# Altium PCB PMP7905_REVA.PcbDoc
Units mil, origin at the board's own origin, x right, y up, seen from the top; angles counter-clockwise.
Board outline 3200 x 2800 mil, 4 copper layers (Top Layer, MidLayer1, MidLayer2, Bottom Layer), stack 62 mil thick; 91 components, 31 nets, 190 pads, 69 vias.
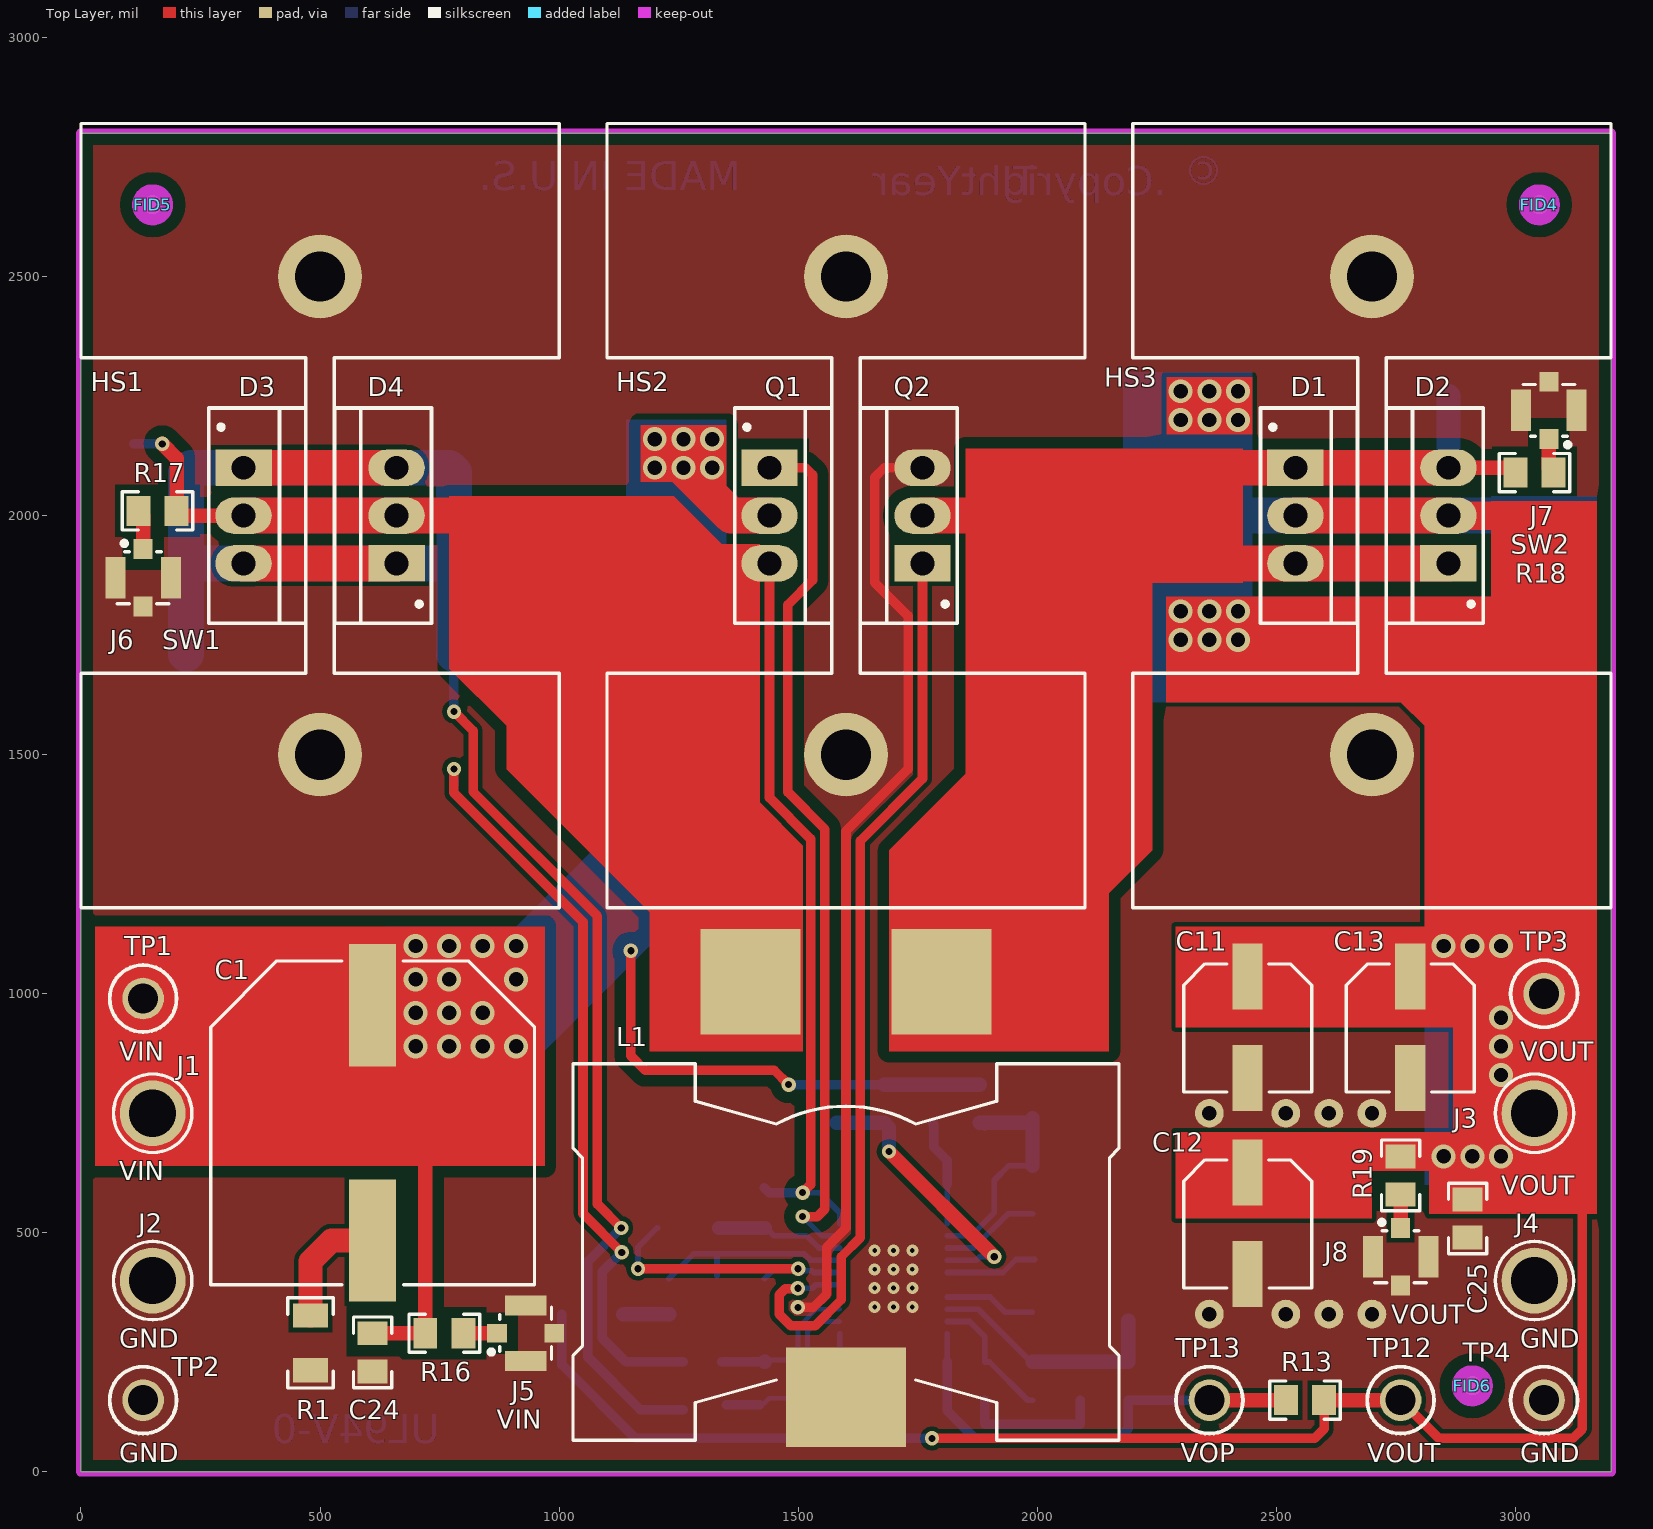
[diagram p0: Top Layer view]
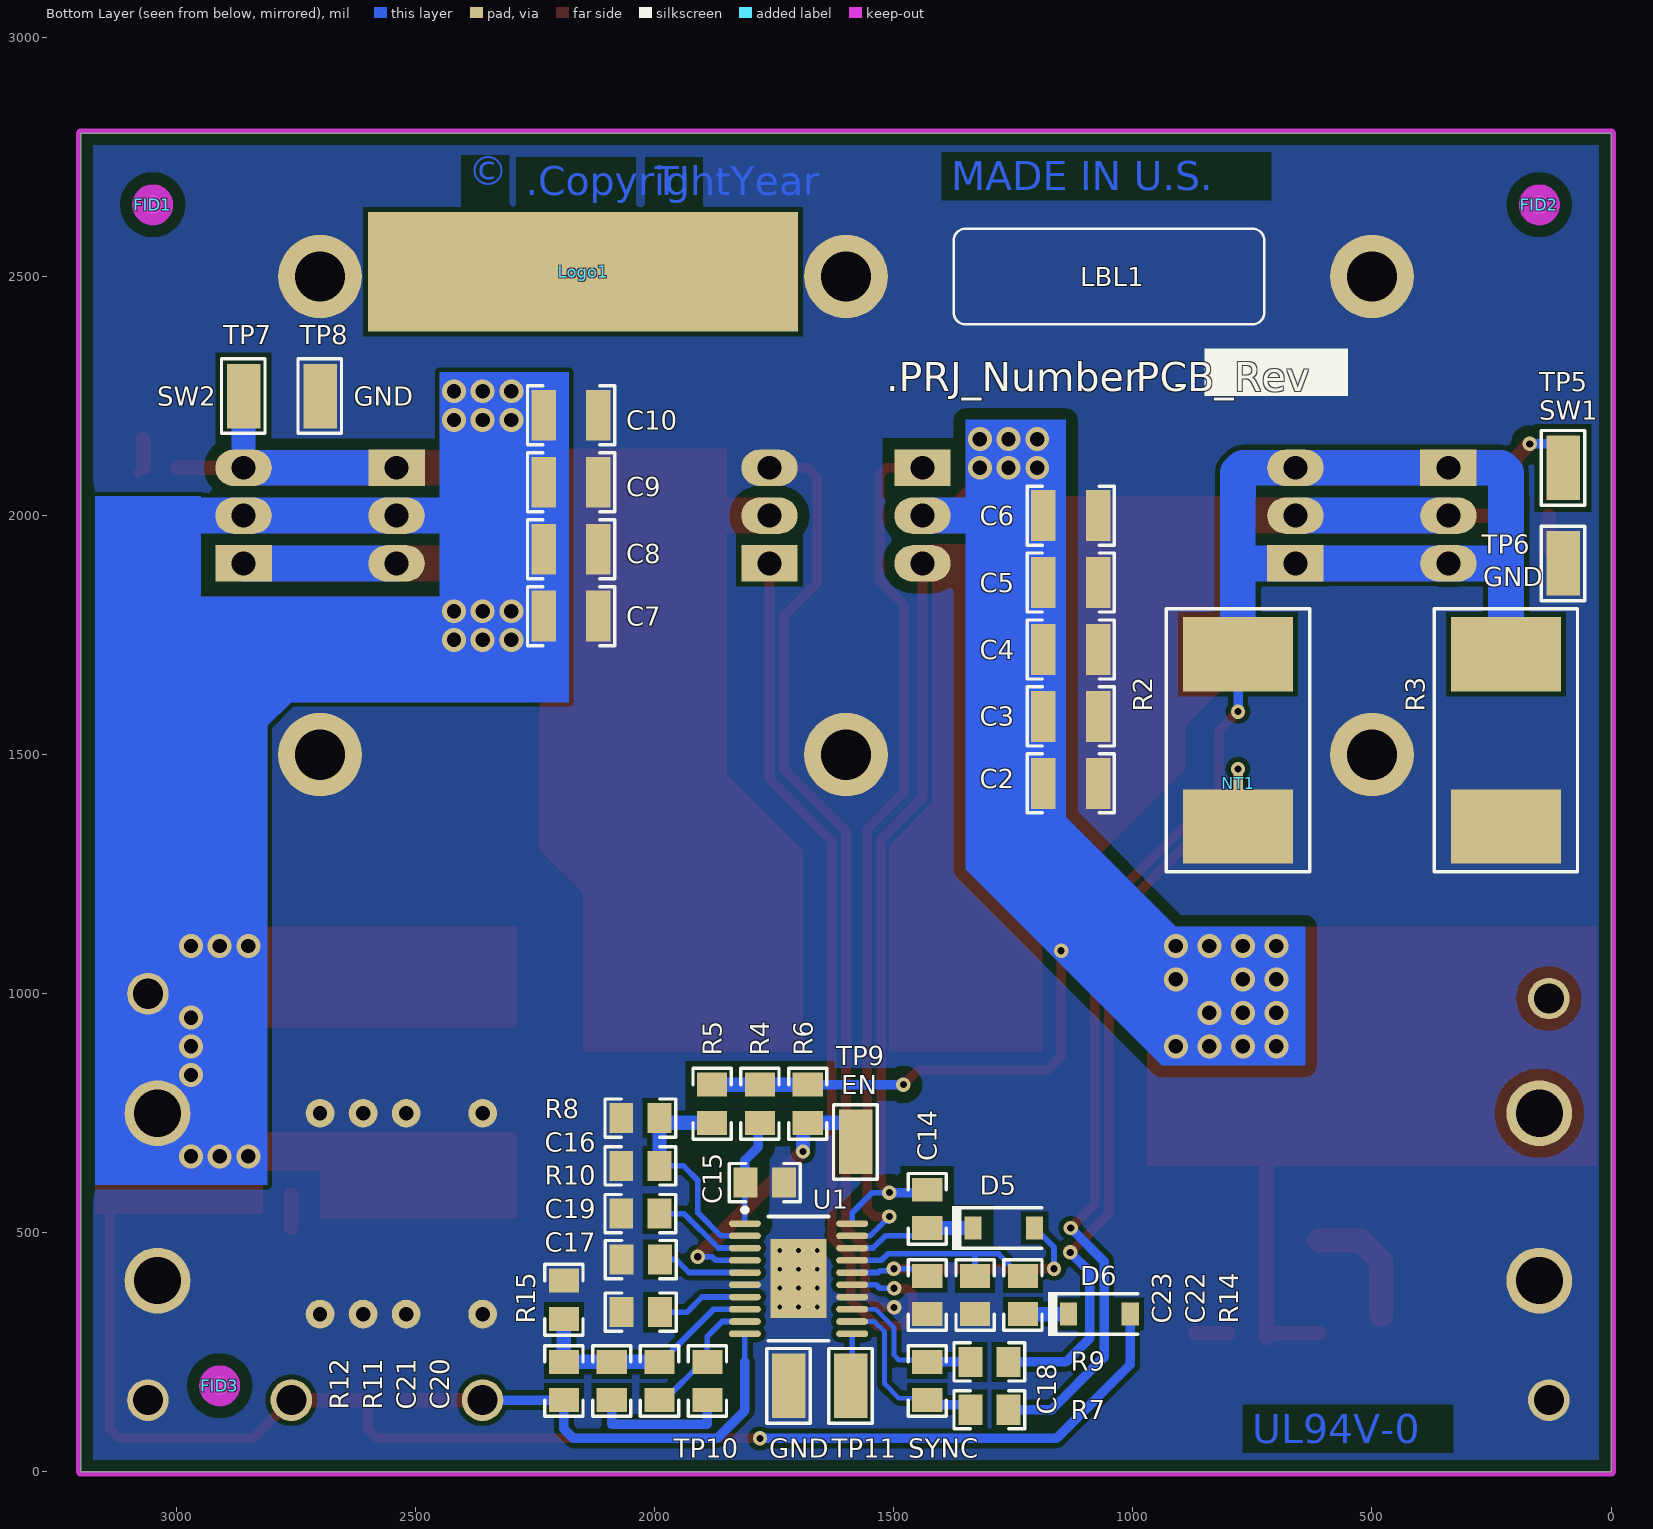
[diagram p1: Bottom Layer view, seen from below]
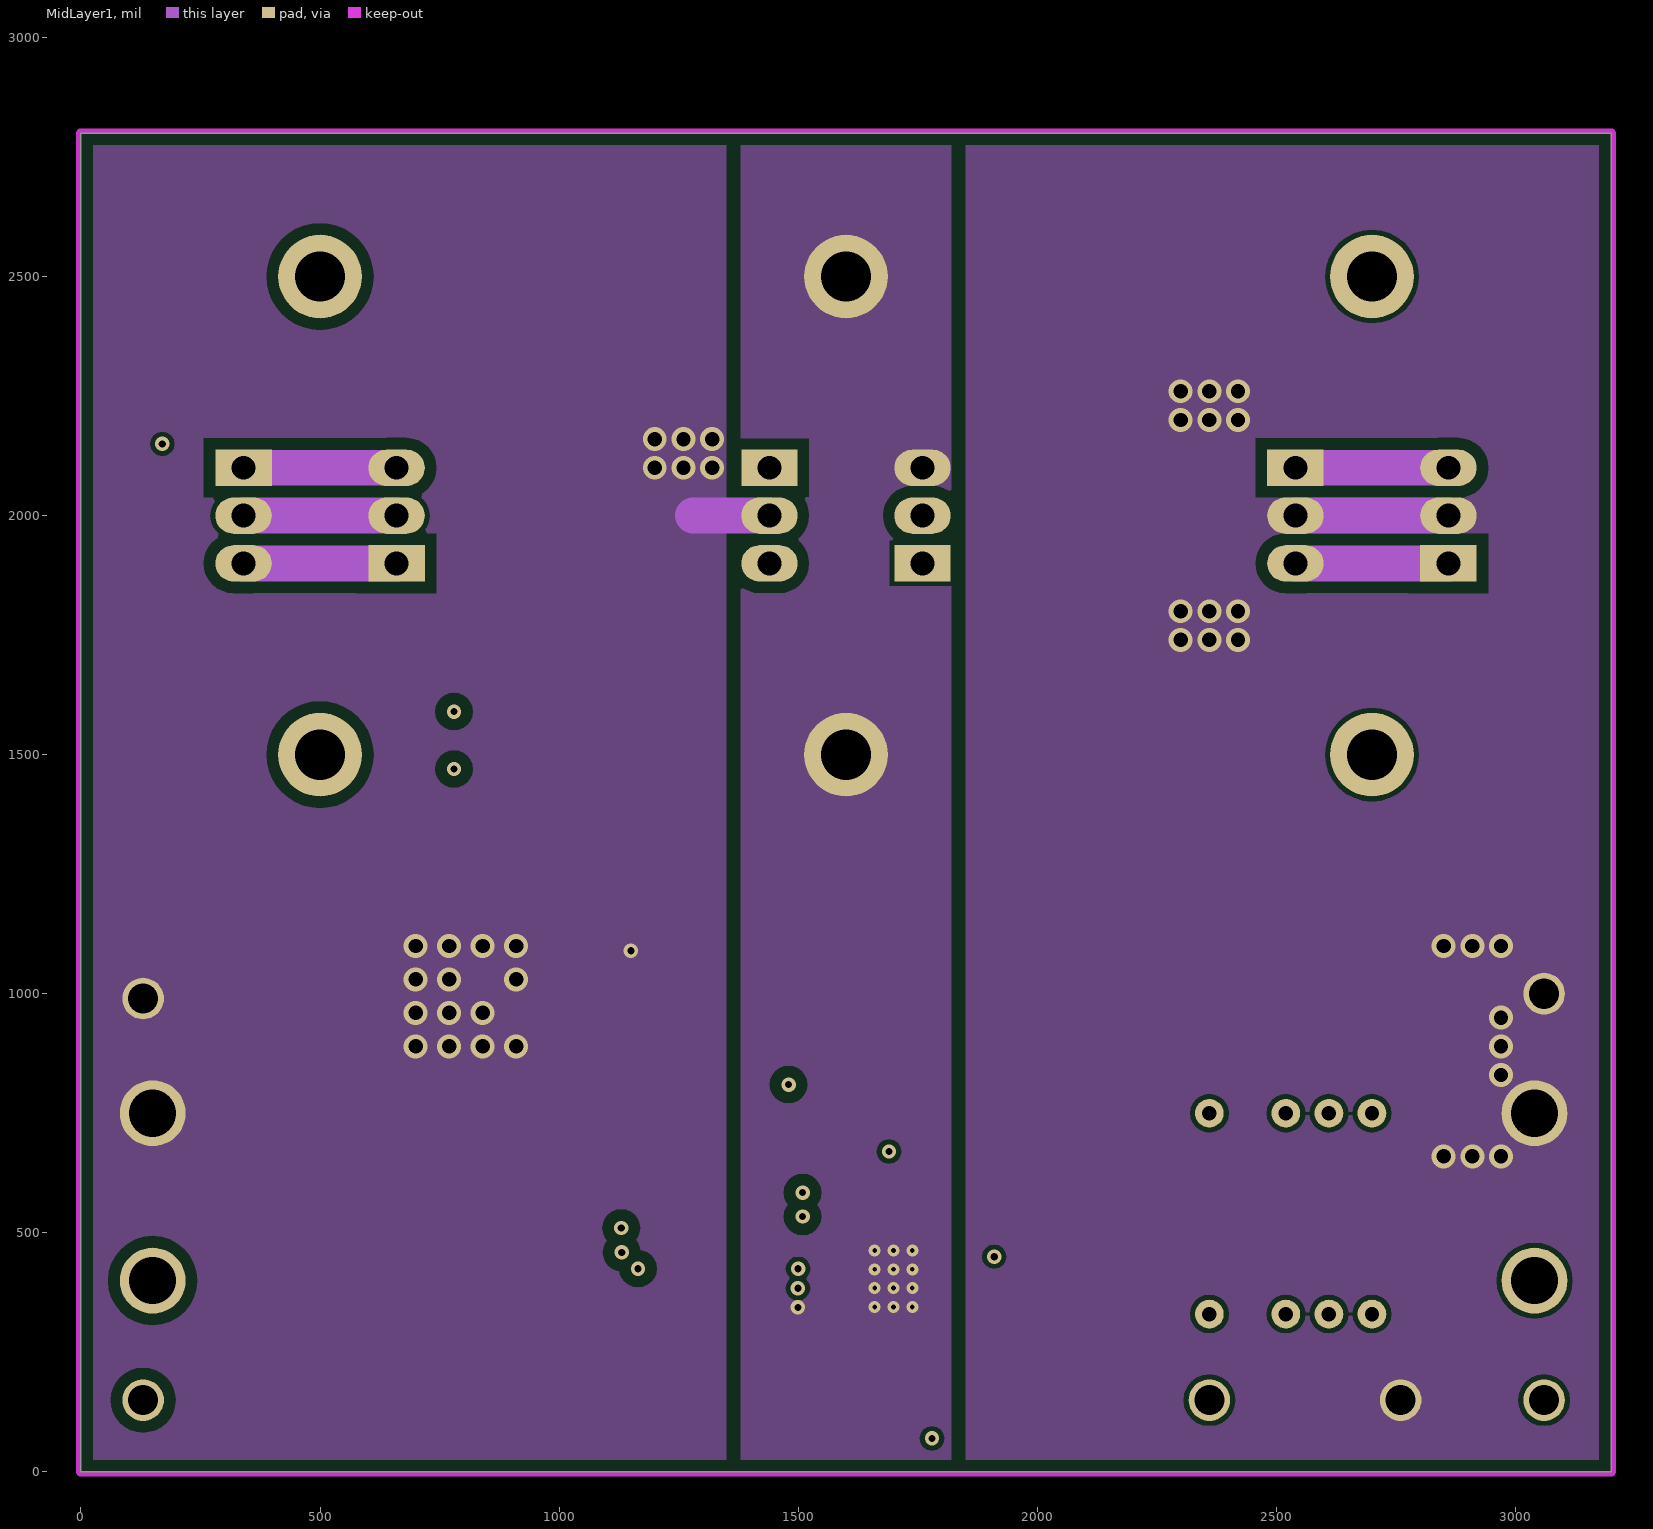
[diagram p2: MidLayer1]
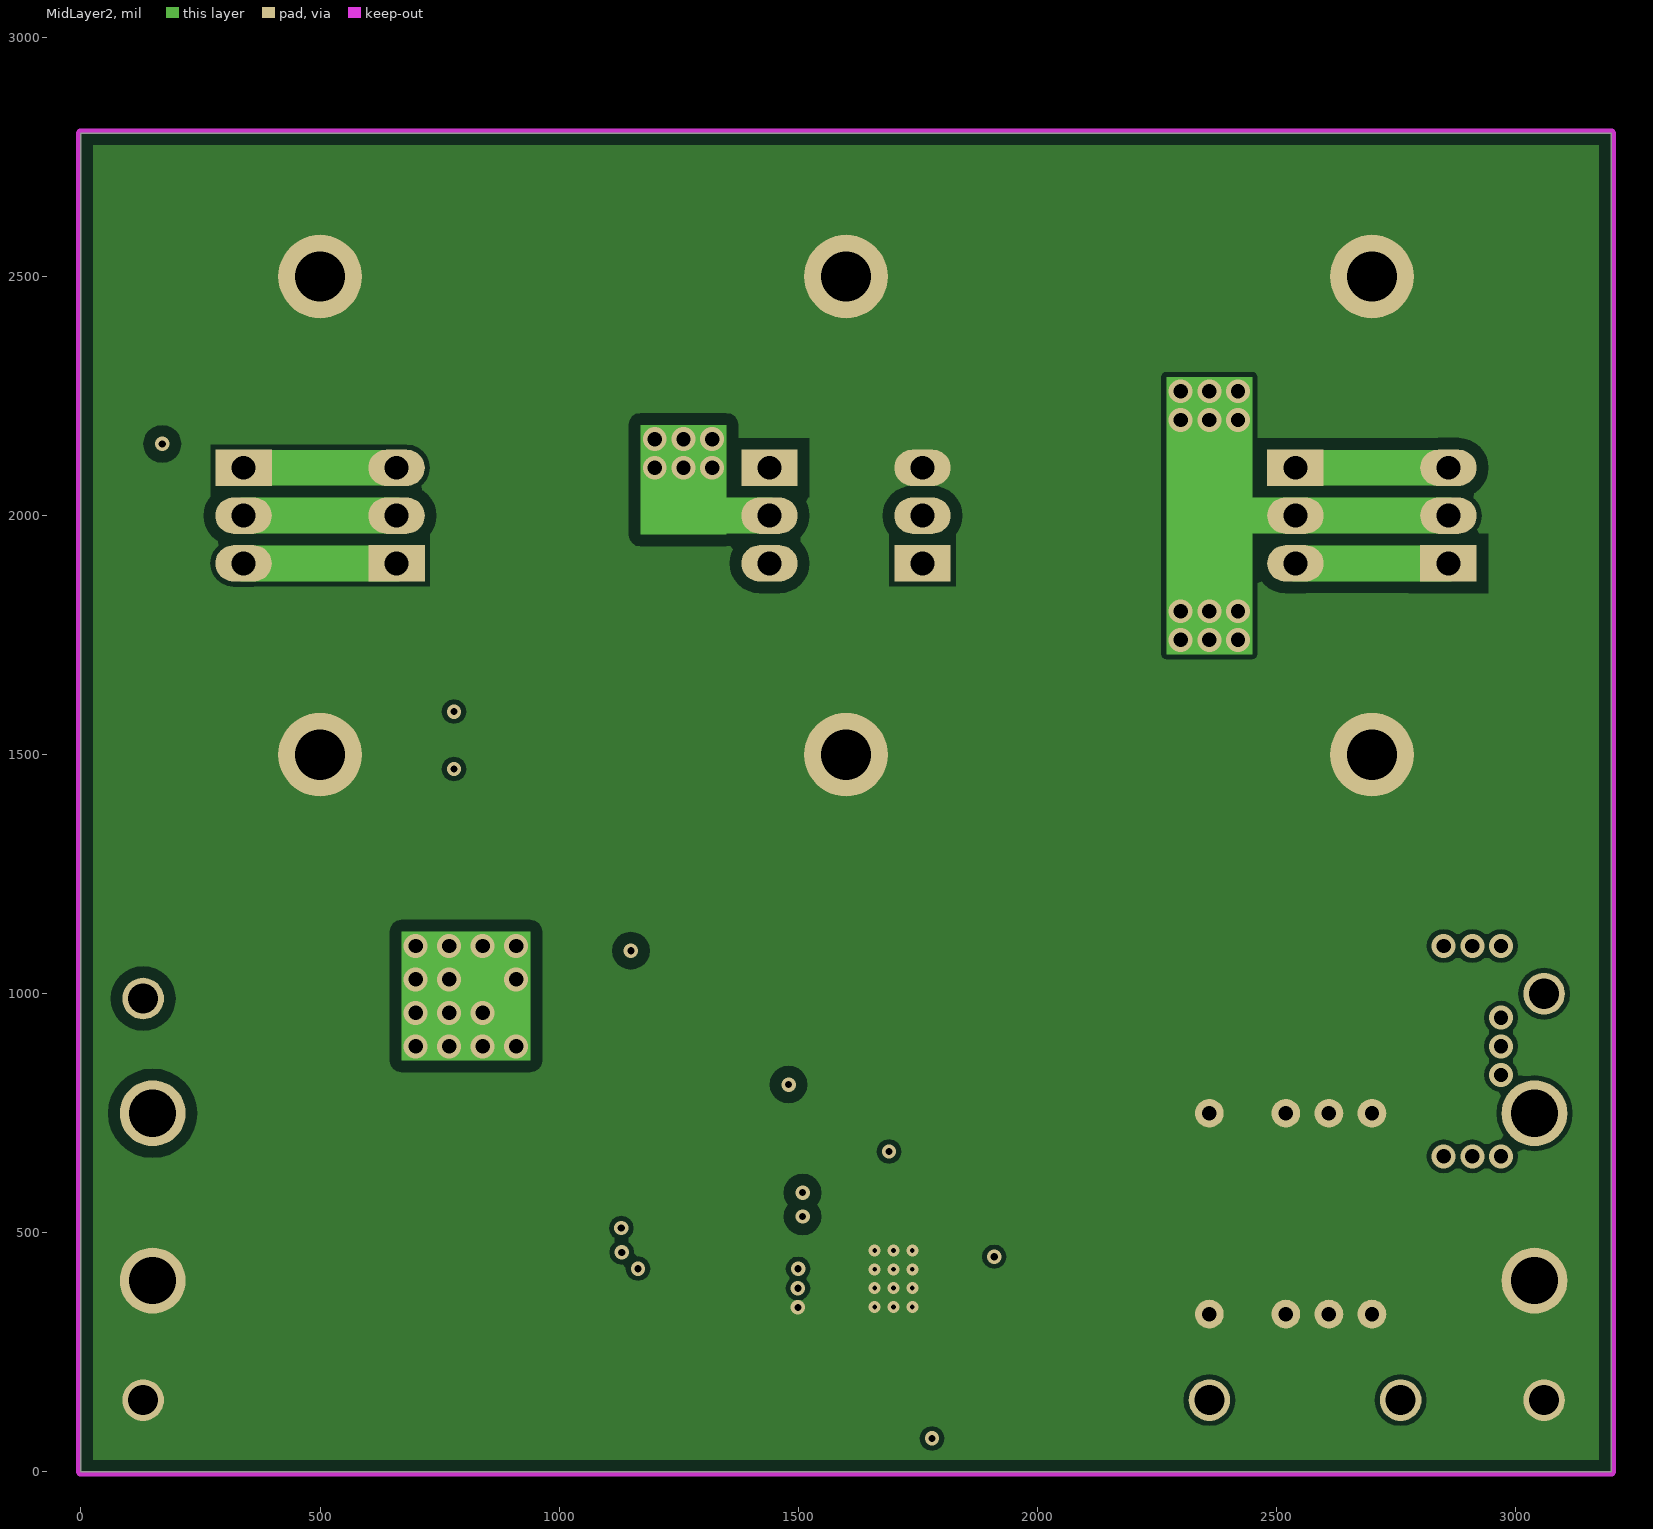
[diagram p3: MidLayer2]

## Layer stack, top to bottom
Top Layer: signal copper 2.8
Dielectric: core 12.6, FR-4, Dk 4.8
MidLayer1: signal copper 1.4
Dielectric: prepreg 28.4, FR-4, Dk 4.8
MidLayer2: signal copper 1.4
Dielectric: core 12.6, FR-4, Dk 4.8
Bottom Layer: signal copper 2.8

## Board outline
0,0 3200,0 3200,2800 0,2800

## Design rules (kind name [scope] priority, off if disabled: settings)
AcuteAngle [All] p1: minimum=4.50000000000000E+0001 checktracksonly=FALSE
AssemblyTestPointUsage [All] p1: valid=2
Clearance Clearance_A-1JB [HasFootprint('A-1JB') vs InNetClass('24mil')] p1: gap=17.5
Clearance Clearance_MXA20A_N [HasFootprint('MXA20A_N') vs InNetClass('24mil')] p2: gap=11
Clearance Clearance_HB_VCCX [InNet('HB') vs InNet('VCCX')] p3: gap=12.5
Clearance Clearance_UVLO_VINF [InNet('UVLO') vs InNet('VINF')] p4: gap=12
Clearance Clearance_10mil_24mil [InNetClass('10mil') vs InNetClass('24mil')] p5: gap=24
Clearance Clearance_BoardEdge_MountingHoles [OnCopper and InComponentClass('Mounting Holes') vs IsKeepOut] p6: gap=40
Clearance Clearance_BoardEdge_Poly [OnCopper and (InPoly or IsRegion) vs IsKeepOut] p7: gap=25
Clearance Clearance_BoardEdge [OnCopper and Not InComponentClass('Logo') and not InComponentClass('FiducialMark') and not InRegion(1000,500,4000,800) vs IsKeepOut] p8: gap=50
Clearance [All] p9: gap=10
ComponentClearance ComponentClearance_NetTie [HasFootprint('Net-Tie_20mil') vs HasFootprint('4527')] p1: gap=0 collisioncheckmode=3 verticalgap=0 showdistances=FALSE
ComponentClearance ComponentClearance_Fiducial_HS [HasFootprint('Fiducial10-20_TopLayerKeepOutOnly') vs HasFootprint('HS-TO-220-VERT-1')] p2: gap=0 collisioncheckmode=3 verticalgap=0 showdistances=FALSE
ComponentClearance ComponentClearance_Fiducial [HasFootprint('Fiducial10-20_TopLayerKeepOutOnly')] p3: gap=40 collisioncheckmode=3 verticalgap=0 showdistances=FALSE
ComponentClearance ComponentClearance_TO-220 [HasFootprint('TO-220AB') vs HasFootprint('TO-220AB')] p4: gap=60 collisioncheckmode=3 verticalgap=10 showdistances=FALSE
ComponentClearance ComponentClearance_HeatSink [HasFootprint('HS-TO-220-VERT-1') vs HasFootprint('TO-220AB')] p5: gap=0 collisioncheckmode=3 verticalgap=10 showdistances=FALSE
ComponentClearance ComponentClearance_Logo [InComponentClass(Logo)] p6: gap=50 collisioncheckmode=3 verticalgap=10 showdistances=FALSE
ComponentClearance ComponentClearance_ScrewToNut [(HasFootprint('NY PMS 440 0025 PH')) vs (HasFootprint('Keystone_1902C'))] p7: gap=5 collisioncheckmode=3 verticalgap=10 showdistances=FALSE
ComponentClearance ComponentClearance_MountingHoles [InComponentClass('Mounting Holes')] p8: gap=150 collisioncheckmode=3 verticalgap=100000 showdistances=FALSE
ComponentClearance ComponentClearance_SmallPassives [HasFootprint('0201*') or HasFootprint('0402*') or HasFootprint('0508') or HasFootprint('0603*') or HasFootprint('0612') or HasFootprint('0805*') or HasFootprint('0815*') or HasFootprint('0830*') or HasFootprint('1206*') or HasFootprint('1210*') or HasFootprint('1808*') or HasFootprint('1812*') or HasFootprint('1825*') or HasFootprint('2010*') or HasFootprint('2220*') or HasFootprint('2225*') or HasFootprint('2512*') or HasFootprint('2728*') or HasFootprint('3518*') vs HasFootprint('0201*') or HasFootprint('0402*') or HasFootprint('0508') or HasFootprint('0603*') or HasFootprint('0612') or HasFootprint('0805*') or HasFootprint('0815*') or HasFootprint('0830*') or HasFootprint('1206*') or HasFootprint('1210*') or HasFootprint('1808*') or HasFootprint('1812*') or HasFootprint('1825*') or HasFootprint('2010*') or HasFootprint('2220*') or HasFootprint('2225*') or HasFootprint('2512*') or HasFootprint('2728*') or HasFootprint('3518*')] p9: gap=20 collisioncheckmode=3 verticalgap=10 showdistances=FALSE
ComponentClearance ComponentClearance_THtoSMT [IsThruComponent vs IsSMTComponent] p10: gap=50 collisioncheckmode=3 verticalgap=50 showdistances=FALSE
ComponentClearance ComponentClearance_THtoTH [IsThruComponent vs IsThruComponent] p11: gap=100 collisioncheckmode=3 verticalgap=50 showdistances=FALSE
ComponentClearance [All] p12: gap=40 collisioncheckmode=3 verticalgap=10 showdistances=FALSE
DiffPairsRouting [All] p1: maxlimit=100 minlimit=10 mostfreqgap=10 maxuncoupledlength=1000
FabricationTestPointUsage TestPointUsage [All] p1: valid=2 allowmultiple=FALSE
FabricationTestpoint Testpoint [All] p1: side=3 testpointundercomponent=TRUE minsize=40 maxsize=100 preferedsize=60 minholesize=0 maxholesize=40 preferedholesize=32 testpointgrid=1 allowsidetop=TRUE allowsidebottom=TRUE usegrid=TRUE gridtolerance=0.01
FanoutControl Fanout_LCC [IsLCC] p1: bgadir=Out bgaviamode=Centered fanoutstyle=Auto fanoutdirection=Alternating viagrid=1 // Fanout_LCC (Default Rule)
FanoutControl Fanout_BGA [IsBGA] p2: bgadir=Out bgaviamode=Centered fanoutstyle=Auto fanoutdirection=Alternating viagrid=1 // Fanout_BGA (Default Rule)
FanoutControl Fanout_Default [All] p4: bgadir=Out bgaviamode=Centered fanoutstyle=Auto fanoutdirection=Alternating viagrid=1 // Fanout_Default (Default Rule)
FanoutControl Fanout_Small [(CompPinCount < 5)] p5: bgadir=Out bgaviamode=Centered fanoutstyle=Auto fanoutdirection=OutThenIn viagrid=1 // Fanout_Small (Default Rule)
HoleSize [All] p1: absolutevalues=TRUE maxlimit=251 minlimit=8 maxpercent=80.000 minpercent=20.000
MinimumAnnularRing [All] p1: minimumring=7.5
MinimumSolderMaskSliver MinimumSolderMaskSliver_Logo [InComponentClass('Logo') vs InComponentClass('Logo')] p1: minsoldermaskwidth=0.7
MinimumSolderMaskSliver [All] p2: minsoldermaskwidth=4
PlaneConnect [All] p1: planeconnectstyle=Direct reliefexpansion=10 reliefentries=4 reliefconductorwidth=10 reliefairgap=10
PolygonConnect [All] p1: connectstyle=Direct reliefconductorwidth=10 reliefentries=4 polygonreliefangle="90 Angle" airgapwidth=10
RoutingVias [All] p1: holewidth=16 width=34 viastyle="Through Hole" minholewidth=8 minwidth=25 maxholewidth=40 maxwidth=65
SMDToCorner [All] p1: distance=30000
SilkToSilkClearance [All] p1: silktosilkclearance=5
SilkscreenOverComponentPads [All] p1: minsilkscreentomaskgap=5
SolderMaskExpansion [All] p1: expansion=3
Width [All] p1: maxlimit=100 minlimit=6 preferedwidth=10 checkconnectedcopper=TRUE
14 further rules are at their usual default settings.

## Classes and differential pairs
net class 24mil: HB HO SR1 SR2 SW1 SW2 VIN VINF VIR
net class 10mil: CMP COMP CS CSG CSN CSR EN FB GND LO RAMP RCIN RT SS SYNC UVLO VCC VCCD VCCX VOP VOR VOUT
component class Logo: Logo1
component class PMP7905_REVA_Hardware: FID1 FID2 FID3 FID4 FID5 FID6 HS1 HS2 HS3 LBL1 Logo1 ZZ1 ZZ2 ZZ3 ZZ4
component class FiducialMark: FID1 FID2 FID3 FID4 FID5 FID6
component class AssemblyNote: ZZ1 ZZ2 ZZ3 ZZ4
component class Label: LBL1

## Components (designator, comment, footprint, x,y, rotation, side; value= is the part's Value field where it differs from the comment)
C1 "EEV-FK2A101M" SM_RADIAL_J16 610,730 r270 top
C2 "C3225X7S2A475M" 1210 1130,1440 r180 bottom
C3 "C3225X7S2A475M" 1210 1130,1580 r180 bottom
C4 "C3225X7S2A475M" 1210 1130,1720 r180 bottom
C5 "C3225X7S2A475M" 1210 1130,1860 r180 bottom
C6 "C3225X7S2A475M" 1210 1130,2000 r180 bottom
C7 "GRM32ER61C476ME15L" 1210 2174.86,1789.77 r180 bottom
C8 "GRM32ER61C476ME15L" 1210 2174.85,1929.78 r180 bottom
C9 "GRM32ER61C476ME15L" 1210 2174.86,2069.77 r180 bottom
C10 "GRM32ER61C476ME15L" 1210 2174.86,2209.77 r180 bottom
C11 "APXE160ARA101MF80G" CAPSMT_62_F80 2440,930 r270 top
C12 "APXE160ARA101MF80G" CAPSMT_62_F80 2440,520 r270 top
C13 "APXE160ARA101MF80G" CAPSMT_62_F80 2780,930 r270 top
C14 "C2012X7R1E104K" 0805_HV 1430,550 r90 bottom
C15 "C2012X7R2A104K" 0805_HV 1770,605 r180 bottom
C16 "C2012X7R1E104K" 0805_HV 2030,640 r0 bottom
C17 "C2012X7R1E104K" 0805_HV 2029.32,334.01 r180 bottom
C18 "GRM216R71E102KA01D" 0805_HV 1430,190 r90 bottom
C19 "GRM2165C1H751JA01D" 0805_HV 2029.32,444.01 r180 bottom
C20 "GRM219R71E473KA01D" 0805_HV 1890,190 r90 bottom
C21 "C2012C0G1H101J" 0805_HV 1990,190 r270 bottom
C22 "C2012X7R1E105K" 0805_HV 1330,370 r270 bottom
C23 "C2012X7R1E105K" 0805_HV 1430,370 r270 bottom
C24 "C2012X7R2A104K" 0805_HV 610,250 r270 top
C25 "C2012X7R2A104K" 0805_HV 2900,530 r270 top
D1 "MBR2030CTL" TO-220AB 2540,2000 r270 top locked
D2 "MBR2030CTL" TO-220AB 2860,2000 r90 top locked
D3 "MBR30H100CT" TO-220AB 340,2000 r270 top locked
D4 "MBR30H100CT" TO-220AB 660,2000 r90 top locked
D5 "1N4148W-7-F" SOD-123 1270,510 r180 bottom
D6 "1N4148W-7-F" SOD-123 1070,330 r180 bottom
FID1 "Fiducial" Fiducial10-20_TopLayerKeepOutOnly 3050,2650 r180 bottom
FID2 "Fiducial" Fiducial10-20_TopLayerKeepOutOnly 150,2650 r180 bottom
FID3 "Fiducial" Fiducial10-20_TopLayerKeepOutOnly 2910,180 r180 bottom
FID4 "Fiducial" Fiducial10-20_TopLayerKeepOutOnly 3050,2650 r0 top
FID5 "Fiducial" Fiducial10-20_TopLayerKeepOutOnly 150,2650 r0 top
FID6 "Fiducial" Fiducial10-20_TopLayerKeepOutOnly 2910,180 r0 top
HS1 "HS-TO-220-VERT-1" HS-TO-220-VERT-1 500,2000 r90 top locked
HS2 "HS-TO-220-VERT-1" HS-TO-220-VERT-1 1600,2000 r90 top locked
HS3 "HS-TO-220-VERT-1" HS-TO-220-VERT-1 2700,2000 r90 top locked
J1 "VIN" Keystone1598-2 150,750 r0 top
J2 "GND" Keystone1598-2 150,400 r0 top
J3 "VOUT" Keystone1598-2 3040,750 r0 top
J4 "GND" Keystone1598-2 3040,400 r0 top
J5 "VIN" A-1JB 930,290 r180 top
J6 "SW1" A-1JB 130,1870 r90 top
J7 "SW2" A-1JB 3070,2220 r270 top
J8 "VOUT" A-1JB 2760,450 r90 top
L1 "SER2918H-103KL" SER2918 1600,460 r270 top
LBL1 "Size: 0.65\" x 0.20 \"" Label_650x200 1050,2500 r180 bottom
Logo1 "Texas Instruments" TI_Stacked_SolderMask_Small 2150,2510 r180 bottom
NT1 "Net-Tie_20mil" Net-Tie_20mil 780,1440 r90 bottom net-tie
Q1 "IPP045N10N3 G" TO-220AB 1440,2000 r270 top locked
Q2 "IPP034N03L G" TO-220AB 1760,2000 r90 top locked
R1 "CSR1206FKR500" 1206 480,270 r90 top
R2 "WSR3R0150FEA" 4527 780,1530 r90 bottom
R3 "WSR3R0150FEA" 4527 220,1530 r90 bottom
R4 "CRCW08051R00JNEA" 0805_HV 1780,770 r270 bottom
R5 "CRCW080575K0FKEA" 0805_HV 1880,770 r90 bottom
R6 "CRCW08051M00JNEA" 0805_HV 1680,770 r90 bottom
R7 "CRCW08051R00JNEA" 0805_HV 1300,130 r0 bottom
R8 "CRCW080515K0FKEA" 0805_HV 2030,740 r180 bottom
R9 "CRCW08051R00JNEA" 0805_HV 1300,230 r0 bottom
R10 "CRCW080560K4FKEA" 0805_HV 2030,540 r0 bottom
R11 "CRCW08055K60JNEA" 0805_HV 2090,190 r90 bottom
R12 "CRCW080510K7FKEA" 0805_HV 2190,190 r270 bottom
R13 "CRCW080551R0JNEA" 0805_HV 2560,150 r0 top
R14 "CRCW08051R00JNEA" 0805_HV 1230,370 r270 bottom
R15 "CRCW08051K24FKEA" 0805_HV 2190,360 r270 bottom
R16 "CRCW080549R9FKEA" 0805_HV 760,290 r180 top
R17 "CRCW080549R9FKEA" 0805_HV 160,2010 r0 top
R18 "CRCW080549R9FKEA" 0805_HV 3040,2090 r180 top
R19 "CRCW080549R9FKEA" 0805_HV 2760,620 r90 top
TP1 "VIN" Keystone5010 130,990 r0 top
TP2 "GND" Keystone5011 130,150 r0 top
TP3 "VOUT" Keystone5010 3060,1000 r0 top
TP4 "GND" Keystone5011 3060,150 r0 top
TP5 "SW1" Testpoint_Keystone_Miniature 100,2100 r270 bottom
TP6 "GND" Testpoint_Keystone_Miniature 100,1900 r270 bottom
TP7 "SW2" Testpoint_Keystone_Miniature 2860,2250 r270 bottom
TP8 "GND" Testpoint_Keystone_Miniature 2700,2250 r270 bottom
TP9 "EN" Testpoint_Keystone_Miniature 1580,690 r270 bottom
TP10 "GND" Testpoint_Keystone_Miniature 1720,180 r270 bottom
TP11 "SYNC" Testpoint_Keystone_Miniature 1590,180 r270 bottom
TP12 "VOUT" Keystone5012 2760,150 r0 top
TP13 "VOP" Keystone5012 2360,150 r0 top
U1 "LM5118Q1MHX/NOPB" MXA20A_N 1699.32,404.01 r180 bottom
ZZ1 "This Assembly Note is for PCB labels only" AssemblyNoteLabel 185,3938 r0 top
ZZ2 "These assemblies are ESD sensitive, ESD precautions shall be observed." AssemblyNote 185,3829.11 r0 top
ZZ3 "These assemblies must be clean and free from flux and all contaminants. Use of no clean flux is not acceptable." AssemblyNote 185,3740.56 r0 top
ZZ4 "These assemblies must comply with workmanship standards IPC-A-610 Class 2., unless otherwise specified." AssemblyNote 185,3652 r0 top

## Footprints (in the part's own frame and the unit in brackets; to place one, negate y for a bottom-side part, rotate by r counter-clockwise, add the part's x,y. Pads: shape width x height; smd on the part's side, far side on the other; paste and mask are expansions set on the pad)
0805_HV [mil] "0805 with 30mil clearance between pads"
  rect 50x63 smd: 1(-40,0) 2(40,0)
  silkscreen extent -74,-40 74,40, body extent -43,-29 43,29, height 43
1206 [mm] "1206 from SM-752 data"
  rect 1.3x1.85 smd: 1(-1.45,0) 2(1.45,0)
  silkscreen extent -2.4,-1.21 2.4,1.21, body extent -1.7,-0.9 1.7,0.9, height 1.35
1210 [mm] "1210 from SM-752 data"
  rect 1.3x2.7 smd: 1(-1.45,0) 2(1.45,0)
  silkscreen extent -2.32,-1.57 2.32,1.57, body extent -1.7,-1.35 1.7,1.35, height 1.35
4527 [mil] "Vishay recommended land pattern"
  rect 155x230 smd: 1(-180,0) 2(180,0)
  silkscreen extent -275,-150 275,150, body extent -228,-138 227,137, height 96
A-1JB [mm] "Amphenol recommended land pattern"
  rect 1.05x1 smd: 1(1.525,0) 3(-1.525,0)
  rect 2.2x1.05 smd: 2(0,1.475) 4(0,-1.475)
  silkscreen extent -1.38,-1.38 1.95,1.38, body extent -1.38,-1.38 1.38,1.38, height 1.25
AssemblyNote [mil] "Assembly Note"
AssemblyNoteLabel [mil] "Assembly Note for PCB Labels"
CAPSMT_62_F80 [mm] "6.3 x 7.7mm:  Chemi-Con F80"
  rect 3.5x1.6 smd: 1(-2.7,0) 2(2.7,0)
  silkscreen extent -3.36,-3.4 3.44,3.4, body extent -3.41,-3.41 3.44,3.41, height 8
Fiducial10-20_TopLayerKeepOutOnly [mm]
  round 1 smd paste-0.5 mask+0.5: 1(0,0)
  Top Layer keep-out circle w1.178: c0,0 r0.5
HS-TO-220-VERT-1 [mil] "Heat Sink TO-220 Vertical 1 Inch"
  round 175 hole 105: 1(-500,0) 2(500,0)
  silkscreen extent -820,-500 820,500, body extent -820,-500 820,500, height 1000
Keystone1598-2 [mm] "Triple Turret"
  round 3.5 hole 2.5: 1(0,0)
  silkscreen extent -2.08,-2.08 2.08,2.08, body extent -1.6,-1.6 1.59,1.6, height 7.72
Keystone5010 [mil] "Keystone Multipurpose loops"
  round 87 hole 63: 1(0,0)
  silkscreen extent -70,-70 70,70, body extent -63,-63 63,62, height 319
Keystone5011 [mil] "Keystone Multipurpose loops"
  round 87 hole 63: 1(0,0)
  silkscreen extent -70,-70 70,70, body extent -63,-63 63,62, height 319
Keystone5012 [mil] "Keystone Multipurpose loops"
  round 87 hole 63: 1(0,0)
  silkscreen extent -70,-70 70,70, body extent -63,-63 63,62, height 319
Label_650x200 [mil] "Thermal Transfer Label"
  silkscreen extent -325,-100 325,100, body extent -326,-101 326,101, height 1
MXA20A_N [mm] "TSOP, 20-Leads, Body 6.5x4.4mm, Pitch 0.65mm, Exposed Pad, IPC Medium Density"
  oval 1.7x0.35 smd: 1(-2.85,2.925) 2(-2.85,2.275) 3(-2.85,1.625) 4(-2.85,0.975) 5(-2.85,0.325) 6(-2.85,-0.325) 7(-2.85,-0.975) 8(-2.85,-1.625) 9(-2.85,-2.275) 10(-2.85,-2.925) 11(2.85,-2.925) 12(2.85,-2.275) 13(2.85,-1.625) 14(2.85,-0.975) 15(2.85,-0.325) 16(2.85,0.325) 17(2.85,0.975) 18(2.85,1.625) 19(2.85,2.275) 20(2.85,2.925)
  rect 3x4.2 smd: 21(0,0)
  silkscreen extent -2.98,-3.3 1.6,3.77, body extent -2.25,-3.3 2.25,3.3, height 1.1
Net-Tie_20mil [mil] "20mil net tie, no solder mask opening, no solder paste"
  rect 20x20 smd paste-5 mask-5: 1(-10,0) 2(10,0)
  Top Layer region: -6,10 6,10 6,-10 -6,-10
SER2918 [mm] "Coilcraft recommended land pattern.  Document 644-2, rev 12/12/08"
  rect 5.59x5.33 smd: 1(-14.355,5.075) 2(-14.355,-5.075)
  rect 5.28x6.35 smd: 3(7.72,0)
  silkscreen extent -10,-14.5 10,14.5, body extent -16.8,-13.95 11.03,13.95, height 17.78
SM_RADIAL_J16 [mm] "16 x 16.5mm:  Panasonic J16"
  rect 6.5x2.5 smd: 1(-6.25,0) 2(6.25,0)
  silkscreen extent -8.6,-8.6 8.6,8.6, body extent -8.6,-8.6 8.6,8.6, height 17
SOD-123 [mm] "On Semi recommended land pattern"
  rect 0.915x1.22 smd: 1(-1.637,0) 2(1.637,0)
  silkscreen extent -2.74,-1.17 2.03,1.17, body extent -1.93,-0.9 1.93,0.9, height 1.35
Testpoint_Keystone_Miniature [mil] "Miniature SMT test point"
  rect 135x70 smd: 1(0,0)
  silkscreen extent -78,-46 78,45, body extent -53,-20 53,20, height 61
TI_Stacked_SolderMask_Small [mil]
  rect 900x250 smd paste-125 mask-125: 0(0,0)
TO-220AB [mil] "Copied from Altium's version of TO3B"
  rect 76x118.11 hole 50: 1(-100,0)
  oval 76x118.11 hole 50: 2(0,0) 3(100,0)
  silkscreen extent -225,-73 225,130, body extent -221,-59 221,126, height 765

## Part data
C1: "CAP, AL, 100uF, 100V, +/-20%, 0.17 ohm, SMD"
C2 C3 C4 C5 C6: "CAP, CERM, 4.7uF, 100V, +/-20%, X7S, 1210"
C7 C8 C9 C10: "CAP, CERM, 47uF, 16V, +/-20%, X5R, 1210"
C11 C12 C13: "CAP, AL, 100uF, 16V, +/-20%, 0.024 ohm, SMD"
C14 C16 C17: "CAP, CERM, 0.1uF, 25V, +/-10%, X7R, 0805"
C15 C24 C25: "CAP, CERM, 0.1uF, 100V, +/-10%, X7R, 0805"
C18: "CAP, CERM, 1000pF, 25V, +/-10%, X7R, 0805"
C19: "CAP, CERM, 750pF, 50V, +/-5%, C0G/NP0, 0805"
C20: "CAP, CERM, 0.047uF, 25V, +/-10%, X7R, 0805"
C21: "CAP, CERM, 100pF, 50V, +/-5%, C0G/NP0, 0805"
C22 C23: "CAP, CERM, 1uF, 25V, +/-10%, X7R, 0805"
D1 D2: "Diode, Schottky, 30V, 20A, TO-220"
D3 D4: "Diode, Schottky, 100V, 30A, TO-220"
D5 D6: "Diode, Ultrafast, 100V, 0.15A, SOD-123"
FID1 FID2 FID3 FID4 FID5 FID6: "Fiducial mark.  There is nothing to buy or mount."
HS1 HS2 HS3: "Heat Sink TO-220 Vertical 1 Inch"
J1 J2 J3 J4: library part 1598-2, "Terminal, Turret, TH, Triple"
J5 J6 J7 J8: library part A-1JB, "Connector, RF Jack, Vertical, Gold, SMD"
L1: "Inductor, Shielded E Core, Ferrite, 10uH, 28A, 0.0026 ohm, SMD"
LBL1: library part THT-14-423-10, "Thermal Transfer Printable Labels, 0.650\" W x 0.200\" H - 10,000 per roll"
Logo1: library part TI_Logo, "Texas Instrument Corporate Signature"
NT1: "Single point connection between nets."
Q1: "MOSFET, N-CH, 100V, 100A, TO-220"
Q2: "MOSFET, N-CH, 30V, 80A, TO-220"
R1: "RES, 0.5 ohm, 1%, 0.5W, 1206"
R2 R3: "RES, 0.015 ohm, 1%, 3W, 4527"
R4 R7 R9 R14: "RES, 1.0 ohm, 5%, 0.125W, 0805"
R5: "RES, 75.0k ohm, 1%, 0.125W, 0805"
R6: "RES, 1.0Meg ohm, 5%, 0.125W, 0805"
R8: "RES, 15.0k ohm, 1%, 0.125W, 0805"
R10: "RES, 60.4k ohm, 1%, 0.125W, 0805"
R11: "RES, 5.6k ohm, 5%, 0.125W, 0805"
R12: "RES, 10.7k ohm, 1%, 0.125W, 0805"
R13: "RES, 51 ohm, 5%, 0.125W, 0805"
R15: "RES, 1.24k ohm, 1%, 0.125W, 0805"
R16 R17 R18 R19: "RES, 49.9 ohm, 1%, 0.125W, 0805"
TP1 TP3: library part 5010, "Test Point, TH, Multipurpose, Red"
TP2 TP4: library part 5011, "Test Point, TH, Multipurpose, Black"
TP5 TP6 TP7 TP8 TP9 TP10 TP11: library part 5015, "Test Point, SMT, Miniature"
TP12 TP13: library part 5012, "Test Point, TH, Multipurpose, White"
U1: "Wide Voltage Range Buck-Boost Controller, 20-pin TSSOP-EP, Pb-Free"
ZZ1: library part AssemblyNoteLabel
ZZ2 ZZ3 ZZ4: library part AssemblyNote

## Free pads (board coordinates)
  round 60 hole 30: 0(2360,750) 1(2520,750) 2(2610,750) 3(2700,750) 4(2360,330) 5(2700,330) 6(2520,330) 7(2610,330)

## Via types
v1: diameter 50, hole 30, Top Layer to Bottom Layer, 41 vias
v2: diameter 30, hole 15, Top Layer to Bottom Layer, 14 vias
v3: diameter 25, hole 10, Top Layer to Bottom Layer, 12 vias
v4: diameter 30, hole 15, Top Layer to Bottom Layer, tented top, 2 vias

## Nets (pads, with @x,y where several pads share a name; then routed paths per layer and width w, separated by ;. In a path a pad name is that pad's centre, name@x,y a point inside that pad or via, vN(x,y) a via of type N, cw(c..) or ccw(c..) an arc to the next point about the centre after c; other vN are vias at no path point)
CMP: C20.1 R11.1 | length 300
  Bottom Layer w20: C20.1 1890,100 2090,100 R11.1
COMP: C20.2 C21.2 U1.9 | length 277.8
  Bottom Layer w12: U1.9 1858.88,314.45 1890,283.33 C20.2 1900,230 1980,150 C21.2
CS: C18.1 R7.2 U1.12 | length 362.4
  Bottom Layer w10: C18.1@1429.32,144.01 1439.32,154.01 1489.32,154.01 1519.32,184.01 1519.32,293.3 1540.46,314.45 U1.12
  Bottom Layer w20: R7.2@1350,140 C18.1@1420,140
CSG: C18.2 R9.2 U1.13 | length 329.6
  Bottom Layer w10: C18.2@1429.32,224.01 1439.32,234.01 1489.32,234.01 1499.32,244.01 1499.32,301.59 1537.77,340.04 U1.13
  Bottom Layer w20: R9.2 C18.2
CSN: NT1.2 R9.1 | length 1543.1
  Top Layer w20: v4(780,1470) 780,1420 1050,1150 1050,540 v2(1131,459)
  Bottom Layer w20: v2(1131,459) 1090,418 1090,280 1140,230 R9.1
CSR: D3.1 D3.3 D4.1 D4.3 R2.2 R3.2 R7.1 | length 5699.8
  Top Layer w20: v4(780,1590) 820,1550 820,1422.43 1080,1162.43 1080,560 v2(1130,510)
  Top Layer w75: D3.3 D4.1 ; D3.1 D4.3
  MidLayer1 w75: D3.3 D4.1 ; D3.1 D4.3
  MidLayer2 w75: D3.3 D4.1 ; D3.1 D4.3
  Bottom Layer w20: v4(780,1590) R2.2 ; v2(1130,510) 1060,440 1060,240 1170,130 R7.1
  Bottom Layer w75: R3.2 219.44,1710.56 219.44,1900 ; R2.2 780.56,1710.56 780.56,1900 ; 219.44,1900 219.44,2041.77 220,2042.32 220,2090 230,2100 D3.1 D4.3 770,2100 780,2090 780,2042.32 780.56,2041.77 780.56,1900 ; 219.44,1900 D3.3 D4.1 780.56,1900
EN: R6.1 TP9.1 U1.4 | length 576.9
  Top Layer w30: v2(1690,670) v2(1910,450)
  Bottom Layer w12: U1.4 1872.4,442.4 1880,450 v2(1910,450)
  Bottom Layer w30: TP9.1@1580,730 R6.1 1690,720 v2(1690,670)
FB: C21.1 R11.2 R12.1 R15.2 U1.8 | length 509.9
  Bottom Layer w12: U1.8 1863.36,340.04 1863.43,340.1 1876.68,340.1 C21.1@1988.39,228.39
  Bottom Layer w30: C21.1 R12.1 R15.2@2190,316.69
GND: C2.2 C3.2 C4.2 C5.2 C6.2 C7.2 C8.2 C9.2 C10.2 C11.2 C12.2 C13.2 C15.2 C16.2 C17.1 C19.1 C22.2 C23.2 C24.2 C25.2 HS1.1 HS1.2 HS2.1 HS2.2 HS3.1 HS3.2 J2.1 J4.1 J5.2 J5.3 J5.4 J6.2 J6.3 J6.4 J7.2 J7.3 J7.4 J8.2 J8.3 J8.4 L1.3 NT1.1 pad.0 pad.1 pad.2 pad.3 pad.4 pad.5 pad.6 pad.7 Q2.3 R1.1 R2.1 R3.1 R8.1 R10.2 R15.1 TP2.1 TP4.1 TP6.1 TP8.1 TP10.1 U1.6 U1.14 U1.21 | length 1987.7
  Top Layer w20: v2(1499.32,344.01) 1531.59,344.01 1560,372.43 1560,470 1600,510 1600,1340 1730,1470 1730,1790 1660,1860 1660,2080 1680,2100 Q2.3
  other v3: 1659.95,344.96 1699.32,344.96 1738.69,344.96 1659.95,384.33 1699.32,384.33 1738.69,384.33 1659.95,423.7 1699.32,423.7 1738.69,423.7 1659.95,463.07 1699.32,463.07 1738.69,463.07
HB: C14.1 D5.1 U1.18 | length 272.4
  Bottom Layer w12: C14.1@1429.32,514.01 1449.32,494.01 1517.43,494.01 1543.45,467.99 U1.18
  Bottom Layer w30: D5.1 C14.1
HO: Q1.1 U1.19 | length 1842.6
  Top Layer w20: Q1.1 1515,2100 1530,2085 1530,1865 1478.5,1813.5 1478.5,1421.5 1556,1344 1556,549.78 1540.24,534.01 v2(1509.32,534.01)
  Bottom Layer w12: v2@1509.32,524.01 v2(1509.32,534.01) 1549.75,493.58 U1.19
LO: Q2.1 U1.15 | length 1954.7
  Top Layer w20: v2(1499.32,384.01) v2@1503.33,380 ; v2@1500,383.33 1473.33,383.33 1460,370 1460,330 1484,306 1536,306 1590,360 1590,450 1630,490 1630,1320 1760,1450 Q2.1
  Bottom Layer w12: v2(1499.32,384.01) 1529.32,384.01 1536.52,391.22 U1.15
RAMP: C19.2 U1.5 | length 194.6
  Bottom Layer w12: U1.5 1928.11,416.81 1955.32,444.01 C19.2@1994.87,444.01
RCIN: C1.2 R1.2 | length 261.1
  Top Layer w50: R1.2 480,440 523.94,483.94 C1.2
RT: R10.1 U1.3 | length 208.3
  Bottom Layer w12: U1.3 1866.88,467.99 1938.89,540 R10.1
SR1: J6.1 R17.1 | length 70
  Top Layer w30: J6.1 R17.1@130,2000
SR2: J7.1 R18.1 | length 74.1
  Top Layer w20: R18.1@3070,2100 R18.1
  Top Layer w30: R18.1@3070,2100 J7.1
SS: C17.2 U1.7 | length 190.9
  Bottom Layer w12: U1.7 1901.06,365.63 1932.67,334.01 C17.2
SW1: C14.2 D3.2 D4.2 L1.2 Q1.3 R17.2 TP5.1 U1.20 | length 3604.4
  Top Layer w20: Q1.3 1440,1410 1526,1324 1526,600.7 v2(1509.32,584.01)
  Top Layer w30: v2(170,2150) 200,2120 R17.2 ; R17.2@198.57,2000 D3.2
  Top Layer w75: D3.2 D4.2 800,2000 ; 1170,1900 Q1.3
  MidLayer1 w75: D3.2 D4.2
  MidLayer2 w75: D3.2 D4.2
  Bottom Layer w12: v2(1509.32,584.01) 1544.91,584.01 1587.11,541.81 U1.20
  Bottom Layer w20: TP5.1@110,2150 v2(170,2150) ; C14.2@1429.32,594.01 1439.32,584.01 v2(1509.32,584.01)
  Bottom Layer w75: D3.2 D4.2
SW2: D1.1 D1.3 D2.1 D2.3 L1.1 Q2.2 R18.2 TP7.1 | length 3266.7
  Top Layer w30: D2.3 R18.2@2996.69,2100
  Top Layer w75: Q2.2 1900,2000 ; 2400,1900 D1.3 D2.1 ; 2400,2100 D1.1 D2.3
  MidLayer1 w75: D1.3 D2.1 ; D1.1 D2.3
  MidLayer2 w75: D1.3 D2.1 ; D1.1 D2.3
  Bottom Layer w50: D2.3 TP7.1
  Bottom Layer w75: D1.3 D2.1 ; D1.1 D2.3
SYNC: TP11.1 U1.11 | length 108.9
  Bottom Layer w12: TP11.1@1587.11,180 U1.11
UVLO: C16.1 R5.1 R8.2 U1.2 | length 508.1
  Bottom Layer w12: U1.2 1861.35,493.58 1910,542.23 1910,610 1940,640 C16.1 ; R5.1@1879.32,730 R5.1@1890,719.32
  Bottom Layer w30: R5.1 1980,730 R8.2 C16.1
VCC: C23.1 D5.2 U1.16 | length 606.9
  Top Layer w20: v2(1165,425) v2(1499.95,424.96)
  Bottom Layer w12: v2(1165,425) 1165,470 1205,510 D5.2 ; C23.1@1429.32,404.01 1450.26,424.96 v2(1499.95,424.96) 1504.51,420.4 1529.32,420.4 1532.91,416.81 U1.16
VCCD: D6.1 R14.2 | length 95.5
  Bottom Layer w30: D6.1 R14.2
VCCX: C22.1 R14.1 U1.17 | length 430.9
  Bottom Layer w12: R14.1@1229.32,404.01 1281.26,455.96 1330,455.96 ; C22.1 1330,455.96 ; U1.17 1526.35,442.4 1512.79,455.96 1330,455.96
VIN: C1.1 C2.1 C3.1 C4.1 C5.1 C6.1 C24.1 J1.1 Q1.2 R4.1 R5.2 R6.2 R16.2 TP1.1 | length 2243.3
  Top Layer w20: v2(1150,1090) 1150,870 1180,840 1450,840 v2(1480,810)
  Top Layer w30: C24.1 R16.2 ; R16.2@720,280 720,670
  Top Layer w75: v1(1260,2100) 1360,2000 Q1.2
  MidLayer1 w75: 1280,2000 Q1.2
  MidLayer2 w75: 1300,2130 v1@1310,2120 ; 1310,2000 Q1.2
  Bottom Layer w20: v2(1480,810) R6.2
  Bottom Layer w30: R6.2 R5.2
  Bottom Layer w75: C6.1@1197.09,2000 Q1.2
  other v1: 700,890 770,890 840,890 910,890 700,960 770,960 840,960 700,1030 770,1030 910,1030 700,1100 770,1100 840,1100 910,1100 1200,2100 1320,2100 1200,2160 1260,2160 1320,2160
VINF: C15.1 R4.2 U1.1 | length 223.9
  Bottom Layer w12: U1.1 C15.1@1811.52,601.81
  Bottom Layer w20: R4.2 1783.33,726.67 1783.33,680 1811.52,651.81 C15.1@1811.52,601.81
VIR: J5.1 R16.1 | length 70
  Top Layer w30: R16.1 J5.1
VOP: R12.2 R13.1 TP13.1 U1.10 | length 958.1
  Top Layer w30: TP13.1 R13.1
  Bottom Layer w12: 1811.52,230 U1.10
  Bottom Layer w20: 1811.52,230 1811.52,128.48 1870,70 2170,70 2190,90 R12.2@2190,146.69 ; R12.2 TP13.1
VOR: J8.1 R19.1 | length 70
  Top Layer w30: J8.1 R19.1
VOUT: C7.1 C8.1 C9.1 C10.1 C11.1 C12.1 C13.1 C25.1 D1.2 D2.2 D6.2 J3.1 R13.2 R19.2 TP3.1 TP12.1 | length 4803.7
  Top Layer w20: v2(1780,70) 2580,70 2600,90 R13.2 ; TP12.1 2840,70 3120,70 3140,90 3140,550
  Top Layer w30: R13.2 TP12.1
  Top Layer w60: D2.2 3050,2000
  Top Layer w75: D1.2 D2.2
  MidLayer1 w75: D1.2 D2.2
  MidLayer2 w75: 2410,2000 D2.2
  Bottom Layer w20: D6.2 1005.53,224.47 1160,70 v2(1780,70)
  Bottom Layer w75: 2390,2000 D1.2 D2.2 3040,2000
  other v1: 2850,660 2910,660 2970,660 2970,830 2970,890 2970,950 2850,1100 2910,1100 2970,1100 2300,1740 2360,1740 2420,1740 2300,1800 2360,1800 2420,1800 2300,2200 2360,2200 2420,2200 2300,2260 2360,2260 2420,2260
pads on no net: FID1.1 FID2.1 FID3.1 FID4.1 FID5.1 FID6.1 Logo1.0

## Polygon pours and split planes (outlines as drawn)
GND on MidLayer1 "MidLayer1-GND" (solid, pour order 7): 1380,0 1380,2794.74 1820,2794.74 1820,0 1380,0
VOUT on MidLayer1 "MidLayer1-VOUT" (solid, remove dead copper, pour order 2): 1850,10 1850,2800 3200,2800 3200,0 1850,0 1850,10
VIN on MidLayer1 "MidLayer1-VIN" (solid, remove dead copper, pour order 2): 0,10 0,2800 1350,2800 1350,0 0,0 0,10
GND on MidLayer2 "MidLayer2-GND" (solid, remove dead copper, pour order 2): 0,10 0,2800 3200,2800 3200,0 0,0 0,10
GND on Top Layer "Top Layer-GND" (solid, remove dead copper, pour order 4): 0,0 0,2800 3200,2800 3200,0 0,0
GND on Bottom Layer "Bottom Layer-GND" (solid, remove dead copper, pour order 2): 0,10 0,2800 3200,2800 3200,0 0,0 0,10

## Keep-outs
Keep-Out Layer:
  lines w10: -5,0 ccw(c0,0) 0,-5 ; -5,0 ccw(c0,0) 0,-5 ; -5,0 ccw(c0,0) 0,-5 ; -5,0 ccw(c0,0) 0,-5 ; -5,0 ccw(c0,0) 0,-5 ; -5,0 ccw(c0,0) 0,-5 ; -5,0 -5,2800 ; -5,2800 cw(c0,2800) 0,2805 ; -5,2800 cw(c0,2800) 0,2805 ; -5,2800 cw(c0,2800) 0,2805 ; -5,2800 cw(c0,2800) 0,2805 ; -5,2800 cw(c0,2800) 0,2805 ; -5,2800 cw(c0,2800) 0,2805 ; 0,-5 3200,-5 ; 0,2805 3200,2805 ; 3200,-5.01 ccw(c3200,0) 3205,0 ; 3200,-5.01 ccw(c3200,0) 3205,0 ; 3200,-5.01 ccw(c3200,0) 3205,0 ; 3200,-5.01 ccw(c3200,0) 3205,0 ; 3200,-5.01 ccw(c3200,0) 3205,0 ; 3200,-5.01 ccw(c3200,0) 3205,0 ; 3200,2805 cw(c3200,2800) 3205,2800 ; 3200,2805 cw(c3200,2800) 3205,2800 ; 3200,2805 cw(c3200,2800) 3205,2800 ; 3200,2805 cw(c3200,2800) 3205,2800 ; 3200,2805 cw(c3200,2800) 3205,2800 ; 3200,2805 cw(c3200,2800) 3205,2800 ; 3205,0 3205,2800
  text ".Layer_Name" at 577,-858.49 h60

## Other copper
Top Layer:
  rectangle net VIN: 1330,2060 1350,2080
  rectangle net VOUT: 2270,2170 2450,2290
  rectangle net VIN: 1170,2070 1350,2190
  region net VOUT: 3170,1140 2290,1140 2290,930 2870,930 2870,710 2290,710 2290,530 2700,530 2700,630 2820,630 2820,540 3170,540
  region net VIN: 30,640 30,1140 970,1140 970,640
  region net SW1: 1510,880 1510,1310 1420,1400 1420,1940 1340,1940 1240,2040 770,2040 770,1680 890,1560 890,1470 1190,1170 1190,880
  region net SW2: 1690,880 1690,1300 1850,1460 1850,2140 2430,2140 2430,1860 2240,1860 2240,1300 2150,1210 2150,880
  region net VOUT: 2270,1830 2950,1830 2950,2030 3170,2030 3170,1130 2810,1130 2810,1560 2760,1610 2270,1610
  text ".Layer_Name" at 577,-858.49 h60
MidLayer2:
  rectangle net VIN: 670,860 940,1130
  rectangle net VOUT: 2270,1710 2450,2290
  rectangle net VIN: 1170,1960 1350,2190
Bottom Layer:
  region net VOUT: 2180,2300 2450,2300 2450,1830 2950,1830 2950,2040 3170,2040 3170,600 2810,600 2810,1560 2760,1610 2180,1610
  region net VIN: 1140,2200 1350,2200 1350,1260 940,850 640,850 640,1140 910,1140 1140,1370
  text ".VersionControl_RevNumber" at 4021,3060 h60
  text "SVN:" at 4300,3060 h60
  text "MADE IN U.S." at 1380,2680 h60
  text "TI" at 2000,2670 h60
  text ".CopyrightYear" at 2270,2670 h60
  text "©" at 2390,2670 h105
  text "UL94V-0" at 750,60 h60
  text ".Layer_Name" at 577,-858.49 h60

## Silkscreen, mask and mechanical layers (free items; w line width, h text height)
Top Overlay:
  text ".Layer_Name" at 577,-858.49 h60
Bottom Overlay:
  rectangle: 550,2250 850,2350
  text ".PCB_Rev" at 1020,2260 h60
  text ".PRJ_Number" at 1516,2260 h60
  text "-" at 915,2249.5 h60
  text ".Layer_Name" at 577,-858.49 h60
Top Paste:
  text ".Layer_Name" at 577,-858.49 h60
Bottom Paste:
  text ".Layer_Name" at 577,-858.49 h60
Top Solder:
  text ".Layer_Name" at 577,-858.49 h60
  text ".Layer_Name" at 577,-858.49 h60
Bottom Solder:
  text ".Layer_Name" at 577,-858.49 h60
Drill Guide:
  text ".Layer_Name" at 577,-858.49 h60
M1 Board Outline:
  the board outline again, w10
  text ".Layer_Name" at 577,-858.49 h60
M2 Board Dimensions:
  rectangle: -0.5,-285.5 124.5,-160.5
  rectangle: 124.5,-410.5 499.5,-285.5
  lines w7: -0.5,-285.5 999.5,-285.5 ; 124.5,-410.5 124.5,-160.5 ; 249.5,-410.5 249.5,-160.5 ; 499.5,-410.5 499.5,-160.5 ; 749.5,-410.5 749.5,-160.5 ; -0.5,-410.5 999.5,-410.5 999.5,-160.5 -0.5,-160.5 -0.5,-410.5
  lines w10: -0.5,-475.5 -0.5,-455.5 ; 59.5,-485.5 -0.5,-465.5 ; 59.5,-445.5 -0.5,-465.5 ; 223.58,-465.5 -0.5,-465.5 ; 775.42,-465.5 999.5,-465.5 ; 939.5,-485.5 999.5,-465.5 ; 939.5,-445.5 999.5,-465.5 ; 999.5,-475.5 999.5,-455.5
  text "1000 (mil)" at 233.58,-501.49 h60
  text ".Layer_Name" at 577,-858.49 h60
M3 3D STEP Top:
  text ".Layer_Name" at 577,-858.49 h60
M4 3D STEP Bottom:
  text ".Layer_Name" at 577,-858.49 h60
M5 Assembly Top:
  lines w7: 3639,110.5 4764,110.5 ; 3639,233 4761.5,233 ; 3954,-9.5 3954,353 ; 4339,-9.5 3639,-9.5 ; 4339,353 3639,353 ; 3639,-9.5 4764,-9.5 4764,353 3639,353 ; 3639,-9.5 3639,353
  lines w10: -292,-930.17 6308,-930.17 ; -292,-726.83 6310,-726.83 ; -292,-523.5 -292,-1133.5 3713,-1133.5 6310,-1133.5 6310,-523.5 -291.5,-523.5 -291.5,-1133.5 1284,-1133.5 ; 2173,-1133.5 2173,-523.5 ; 3440,-726.83 3440,-523.5 ; 4280,-726.83 4280,-523.5 ; 4902,-1140 4902,-937.17
  text "TABLE 1" at 4026.5,388 h40
  text "Variant" at 3664,278 h40
  text "Label text" at 4099,278 h40
  text "001" at 3731.5,158 h40
  text "ChangeMe!" at 4009,155.5 h40
  text "002" at 3731.5,33 h40
  text "ChangeMe!" at 4004,30.5 h40
  text "COMPONENTS MARKED 'DNP' SHOULD NOT BE POPULATED, AND MAY NOT BE IN BILL OF MATERIALS" at 1153.5,-318.5 h60
  text "ASSEMBLY VARIANT:" at 1153,-434 h60
  text ".VariantName" at 2189,-434 h60
  text "PCB VIEWED FROM TOP SIDE" at -228.5,-655.67 h60
  text "BOARD #:" at 2248,-655.67 h60
  text ".PRJ_Number" at 2793.5,-655.67 h60
  text "REV:" at 3638,-655.67 h60
  text ".PCB_Rev" at 3929.5,-655.67 h60
  text "SVN REV:" at 4476,-655.67 h60
  text ".VersionControl_RevNumber" at 4982,-655.67 h60
  text "IGNORE ->" at -228.5,-858.49 h60
  text "PLOT NAME =" at -228.5,-1064.34 h60
  text ".plot_File_Name" at 577,-1064.34 h60
  text "GENERATED    :" at 2250,-1064.34 h60
  text ".Print_Date" at 3119.5,-1064.34 h60
  text ".Print_Time" at 3848.5,-1064.34 h60
  text "TEXAS INSTRUMENTS" at 5113,-1064.34 h60
M6 Assembly Bottom:
  lines w10: -292.5,-727.33 6309.5,-727.33 ; -290.5,-930.67 6309.5,-930.67 ; 1115.5,-1140.5 1115.5,-937.67 ; 1737.5,-727.33 1737.5,-524 ; 2577.5,-727.33 2577.5,-524 ; 3844.5,-1134 3844.5,-524 ; 4733.5,-1134 6309,-1134 6309,-524 -292.5,-524 -292.5,-1134 2304.5,-1134 6309.5,-1134 6309.5,-524
  text "COMPONENTS MARKED 'DNP' SHOULD NOT BE POPULATED, AND MAY NOT BE IN BILL OF MATERIALS" at 6102,-318 h60
  text ".VariantName" at 5058,-434 h60
  text "ASSEMBLY VARIANT:" at 6097,-434 h60
  text ".VersionControl_RevNumber" at 1035.5,-656.17 h60
  text "SVN REV:" at 1541.5,-656.17 h60
  text ".PCB_Rev" at 2088,-656.17 h60
  text "REV:" at 2379.5,-656.17 h60
  text ".PRJ_Number" at 3224,-656.17 h60
  text "BOARD #:" at 3769.5,-656.17 h60
  text "PCB VIEWED FROM BOTTOM SIDE" at 6246,-656.17 h60
  text "IGNORE ->" at 2547.85,-858.49 h60
  text "TEXAS INSTRUMENTS" at 904.5,-1064.84 h60
  text ".Print_Time" at 2169,-1064.84 h60
  text ".Print_Date" at 2898,-1064.84 h60
  text "GENERATED    :" at 3767.5,-1064.84 h60
  text ".plot_File_Name" at 5440.5,-1064.84 h60
  text "PLOT NAME =" at 6246,-1064.84 h60
M9 Title Sheet:
  drawing of 57 lines, arcs and shapes, not listed
  text "1" at 739.84,8036.5 h70
  text "2" at 3235.5,8036.5 h70
  text "3" at 5724.84,8036.5 h70
  text "4" at 8231.51,8036.5 h70
  text "5" at 10730.5,8036.5 h70
  text "6" at 13235.5,8036.5 h70
  text "This document can handle board shapes up to 7.9in x 10in, although" at 170,7435 h60
  text "our panel vendors top out at 7in x 10in." at 170,7310.94 h60
  text "To re-size the board shape, do the following:" at 225,7186.88 h60
  text "Select lines on M1 Board Outline and delete (easy in single layer mode...shift+s)" at 285,7062.82 h60
  text "Draw a rectangle using lines (example will be for a 4\" x 6\" board" at 285,6938.76 h60
  text "A" at -416.5,6893.5 h70
  text "A" at 14383.5,6893.5 h70
  text "Enter Place Line mode (keyboard pl)" at 495,6814.71 h60
  text "keyboard jo to jump to origin, hit enter" at 495,6690.65 h60
  text "keyboard jl to jump to location, set x to 6000, hit enter twice" at 495,6566.59 h60
  text "keyboard jl to jump to location, set x to 6000 and y to 4000, hit enter twice" at 495,6442.53 h60
  text "keyboard jl to jump to location, set x to 0 and y to 4000, hit enter twice" at 495,6318.47 h60
  text "keyboard jo to jump to origin, hit enter" at 495,6194.41 h60
  text "Hit ESC twice to exit place line mode" at 495,6070.35 h60
  text "Select lines on M1 Board Outline" at 285,5926.3 h60
  text "Menu Design|Board Shape|Define from Selected Objects (keyboard dsd)" at 285,5822.24 h60
  text "To define a Keep-Out that mirrors the board outline:" at 170,5698.18 h60
  text "Menu Design|Board Shape|Create Primitives From Board Shape (keyboard dsp)" at 285,5574.12 h60
  text "Set the Keep-Out Layer as the layer, set width as preferred" at 495,5450.06 h60
  text "Ensure Route Tool Outline is selected, hit enter" at 495,5326 h60
  text "If you re-size the board, don't forget to move the drill table strings on the" at 170,5003 h60
  text "Drill Drawing Layer...they should be just to the right of your board shape" at 363,4897 h60
  text "B" at -416.5,4513.5 h70
  text "B" at 14383.5,4513.5 h70
  text "C" at -416.5,2138.5 h70
  text "C" at 14383.5,2138.5 h70
  text "PROJECT TITLE:" at 11343.5,277.5 h45
  text ".PRJ_Title" at 11393.5,144.17 h70
  text "DESIGNED FOR:" at 11343.5,-23.5 h45
  text ".PRJ_Customer" at 11393.5,-163.5 h70
  text "D" at -416.5,-231.5 h70
  text "D" at 14383.5,-231.5 h70
  text "FILE NAME:" at 11343.5,-323.5 h45
  text ".PCB_File_Name_No_Path" at 11393.5,-443.5 h70
  text "Texas Instruments (TI) and/or its licensors do not warrant the accuracy or completeness of this specification" at 6374,-605.34 h45
  text "ENGINEER:" at 11343.5,-613.5 h45
  text "LAYOUT BY:" at 12848.5,-613.5 h45
  text "or any information contained therein. TI and/or its licensors do not warrant that this design will meet" at 6329.01,-718 h45
  text ".PRJ_Engineer" at 11393.5,-768.49 h70
  text ".PCB_Layout" at 12899,-768.49 h70
  text "the specifications, will be suitable for your application or fit for any particular purpose, or will operate in" at 6329.01,-830.67 h45
  text ".Layer_Name" at 577,-858.49 h60
  text "ALTIUM DESIGNER VERSION:" at 12848.5,-923.5 h45
  text "an implementation. TI and/or its licensors do not warrant that the design is production worthy. You should" at 6329.01,-943.33 h45
  text "completely validate and test your design implementation to confirm the system functionality for your application." at 6374,-1056 h45
  text ".print_Scale" at 11393.5,-1056.83 h70
  text ".Application_BuildNumber" at 12899,-1056.83 h70
  text "1" at 739.84,-1263.5 h70
  text "2" at 3235.5,-1263.5 h70
  text "3" at 5724.84,-1263.5 h70
  text "4" at 8231.51,-1263.5 h70
  text "5" at 10730.5,-1263.5 h70
  text "6" at 13235.5,-1263.5 h70
M10 Fab Notes:
  drawing of 203 lines, arcs and shapes, not listed
  text "DESIGN INFORMATION" at 12381.02,6810 h60
  text "(REFER ALSO ARRAY/PANEL PROFILING INFORMATION)" at 12019.46,6648.29 h60
  text "BOARD SIZE" at 11333.46,6644 h60
  text "2800MIL" at 11795.78,6516.18 h60
  text "X" at 12301.46,6516.18 h60
  text "3200MIL" at 12532.78,6516.18 h60
  text "Number of Layers :" at 11736.46,6319 h60
  text "2" at 12831.27,6309 h60
  text "MIN. TRACK WIDTH:" at 11736.46,6180 h60
  text "10" at 12832.7,6180 h60
  text "MIL" at 12987.46,6180 h60
  text "MIN. CLEARANCE:" at 11736.46,6048 h60
  text "10" at 12832.7,6048 h60
  text "MIL" at 12987.46,6048 h60
  text "MIN. VIA PAD SIZE:" at 11736.46,5916 h60
  text "25" at 12802.71,5916 h60
  text "MIL" at 12987.46,5916 h60
  text "0.05mm (2MIL)" at 12431.46,5774.29 h60
  text "MINIMUM ANNULAR RING" at 11407.23,5770 h60
  text "EXTERNAL" at 13139.46,5770 h60
  text "PER" at 11607.23,5652 h60
  text "IPC-D-275 CLASS 2 LEVEL C" at 11827.23,5652 h60
  text "MIL, HOLES" at 13315.46,5539.71 h60
  text "+/-" at 12923,5539 h60
  text "+/-" at 13777,5539 h60
  text "REGISTRATION TOLERANCES:" at 11407.23,5534 h60
  text "METAL" at 12607,5534 h60
  text "5" at 13183.2,5534 h60
  text "3" at 14016.2,5534 h60
  text "MIL" at 14132.46,5534 h60
  text "MATERIAL:" at 11332.46,5324.54 h60
  text "FR-4 High Tg" at 12318.9,5184.21 h60
  text "X" at 11610,5180 h60
  text "FR-4" at 11793.46,5175.64 h60
  text "OTHER" at 13241.46,5175.64 h60
  text "62 MIL (1.6mm) +/-10%" at 12073.56,5012.92 h60
  text "THICKNESS:" at 11407.23,5008.64 h60
  text "X" at 11945.4,5008.64 h60
  text "OTHER" at 13358.46,5008.64 h60
  text "TOLERANCE:" at 11407.23,4850.64 h60
  text "X" at 12246.53,4850.64 h60
  text "ANSI IPC-6012 TYPE 3 CLASS 2" at 12433.48,4850.64 h60
  text "OTHER +/-" at 12433.46,4694.64 h60
  text "BOW & TWIST:" at 11407.23,4537.64 h60
  text "X" at 12246.53,4537.64 h60
  text "ANSI IPC-6012 TYPE 3 CLASS 2" at 12433.48,4537.64 h60
  text "OTHER +/-" at 12433.46,4379.13 h60
  text "COPPER THICKNESS (FINISHED):" at 11332.46,4243.64 h60
  text "1.4MIL (1oz)" at 12212.46,4090.92 h60
  text "2MIL (1.4oz)" at 12979.46,4090.92 h60
  text "2.8MIL (2oz)" at 13706.46,4090.92 h60
  text "OUTER:" at 11689.46,4086.64 h60
  text "X" at 13580,4080 h60
  text "1.4MIL (1oz)" at 12562.46,3933.92 h60
  text "2.8MIL (2oz)" at 13406.46,3933.92 h60
  text "INNER SIGNAL:" at 11689.46,3929.64 h60
  text "X" at 12435.42,3929.64 h60
  text "DRILLING:" at 11332.46,3790.64 h60
  text "REFERENCE:" at 11407.23,3673.64 h60
  text "X" at 12055.46,3673.64 h60
  text "AS SHOWN" at 12242.46,3673.64 h60
  text "X" at 12956.46,3673.64 h60
  text "NC_DRILL FILES" at 13093.46,3673.64 h60
  text "PTH MIN COPPER THICKNESS:" at 11407.23,3515.64 h60
  text "X" at 12757.46,3515.64 h60
  text "1MIL" at 12894.46,3515.64 h60
  text "OTHER" at 13391.46,3515.64 h60
  text "BOARD FINISH:" at 11332.46,3356.64 h60
  text "SILKSCREEN:" at 11487.68,3238.64 h60
  text "X" at 12436.46,3238.64 h60
  text "TOP" at 12562.46,3238.64 h60
  text "X" at 12946.46,3238.64 h60
  text "BOTTOM" at 13073.46,3238.64 h60
  text "SILKSCREEN COLOR:" at 11487.68,3071.64 h60
  text "X" at 12435.42,3071.64 h60
  text "WHITE" at 12562.46,3071.64 h60
  text "OTHER" at 13073.46,3071.64 h60
  text "SOLDER RESIST COLOR:" at 11487.68,2901.64 h60
  text "X" at 12055.42,2742.44 h60
  text "GREEN" at 12182.46,2742.44 h60
  text "BLUE" at 12773.46,2742.44 h60
  text "OTHER" at 13311.46,2742.44 h60
  text "IMMERSION GOLD (ENIG)" at 12393.46,2553.92 h60
  text "SURFACE FINISH:" at 11332.46,2549.64 h60
  text "X" at 13490,2550 h60
  text "Pb-FREE HASL" at 13625.75,2549.64 h60
  text "OTHER" at 12393.46,2392.64 h60
  text "ARRAY/PANEL:" at 11332.46,2213.64 h60
  text "X" at 12210,2210 h60
  text "CUT AND TRIM PER MECH LAYER 1" at 12393.46,2209.35 h60
  text "N.C. ROUTE" at 12393.46,2057.64 h60
  text "V. SCORE" at 13259.46,2057.64 h60
  text "CERTIFICATION:" at 11332.46,1920.64 h60
  text "MATERIALS AND WORKMANSHIP FOR ALL PCBS" at 12057.46,1920.64 h60
  text "TO MEET OR EXCEED THE REQUIREMENTS OF:" at 12057.46,1822.64 h60
  text "X" at 11683.96,1686.13 h60
  text "ANSI IPC-A-600F CLASS ->" at 11822.96,1686.13 h60
  text "X" at 13462.02,1686.13 h60
  text "2" at 13580.96,1686.14 h60
  text "1" at 13265.96,1684.64 h60
  text "3" at 13934.96,1684.64 h60
  text "X" at 11686.02,1526.64 h60
  text "UL 94V-0" at 11822.96,1526.64 h60
  text "X" at 12498.02,1526.64 h60
  text "RoHS" at 12634.96,1526.64 h60
  text "OTHER" at 13279.36,1526.64 h60
  text "PER ORDER" at 13676.42,1526.64 h60
  text "ADDITIONAL REQUIREMENTS:" at 11332.46,1385.64 h60
  text "MICROSECTION:" at 11407.23,1270.64 h60
  text "YES" at 12312.96,1270.64 h60
  text "REQUIRED" at 13174.46,1114.49 h60
  text "BARE BOARD ELEC. TEST:" at 11407.23,1111.64 h60
  text "NONE" at 12712.96,1111.64 h60
  text "PER ORDER" at 13766.46,1111.64 h60
  text "X" at 12590,1110 h60
  text "MANUFACTURER'S MARKING:" at 11407.23,954.64 h60
  text "RAIL" at 12872.96,950.35 h60
  text "METAL" at 13364.77,950.35 h60
  text "X" at 13740,950 h60
  text "SILK" at 13876.46,950.35 h60
  text ".Layer_Name" at 577,-858.49 h60
M11 Gerber Information:
  lines w10: -292,-930.17 6308,-930.17 ; -292,-726.83 6310,-726.83 ; -292,-523.5 -292,-1133.5 3713,-1133.5 6310,-1133.5 6310,-523.5 -291.5,-523.5 -291.5,-1133.5 1284,-1133.5 ; 2173,-1133.5 2173,-523.5 ; 3440,-726.83 3440,-523.5 ; 4280,-726.83 4280,-523.5 ; 4902,-1140 4902,-937.17
  text "ALL ARTWORK VIEWED FROM TOP SIDE" at -228.5,-655.67 h60
  text "BOARD #:" at 2248,-655.67 h60
  text ".PRJ_Number" at 2793.5,-655.67 h60
  text "REV:" at 3638,-655.67 h60
  text ".PCB_Rev" at 3929.5,-655.67 h60
  text "SVN REV:" at 4476,-655.67 h60
  text ".VersionControl_RevNumber" at 4982,-655.67 h60
  text "LAYER NAME =" at -228.5,-858.49 h60
  text "PLOT NAME =" at -228.5,-1064.34 h60
  text ".plot_File_Name" at 577,-1064.34 h60
  text "GENERATED    :" at 2250,-1064.34 h60
  text ".Print_Date" at 3119.5,-1064.34 h60
  text ".Print_Time" at 3848.5,-1064.34 h60
  text "TEXAS INSTRUMENTS" at 5113,-1064.34 h60
M12 Stackup:
  lines w9: 6820,6557 10640,6557 ; 6820,6717.7 10640,6717.7 ; 6760,5532 ccw(c6812,5532) 6812,5480 10648,5480 ccw(c10648,5532) 10700,5532 10700,6858 ccw(c10648,6858) 10648,6910 6812,6910 ccw(c6812,6858) 6760,6858 6760,5532
  text "The Stackup Legend below this is static." at 7455.5,7144.5 h60
  text "If you change the stackup, update the Legend." at 7465.5,7054.5 h60
  text "Layer Stack Up Detail for: PMP7905_REVA.PcbDoc" at 6820,6759.95 h73
  text "Layer" at 6820,6657.7 h37
  text "Gerber" at 8163.05,6657.7 h37
  text "Copper" at 9000.92,6657.7 h37
  text "Dielectric" at 9899.21,6657.7 h37
  text "Name" at 6820,6583.7 h37
  text "Document" at 8163.05,6583.7 h37
  text "Thickness" at 9000.92,6583.7 h37
  text "Material" at 9899.21,6583.7 h37
  text "Top Solder Mask" at 6820,6478.02 h52
  text "(.GTS)" at 8163.05,6478.02 h52
  text "Solder Resist" at 9899.21,6478.02 h52
  text "Top Layer" at 6820,6329.06 h52
  text "(.GTL)" at 8163.05,6329.06 h52
  text "2.8mil" at 9000.92,6329.06 h52
  text "FR-4" at 9899.21,6254.58 h52
  text "MidLayer1" at 6820,6180.1 h52
  text "(.G1)" at 8163.05,6180.1 h52
  text "1.4mil" at 9000.92,6180.1 h52
  text "FR-4" at 9899.21,6105.63 h52
  text "MidLayer2" at 6820,6031.15 h52
  text "(.G2)" at 8163.05,6031.15 h52
  text "1.4mil" at 9000.92,6031.15 h52
  text "FR-4" at 9899.21,5956.67 h52
  text "Bottom Layer" at 6820,5882.19 h52
  text "(.GBL)" at 8163.05,5882.19 h52
  text "2.8mil" at 9000.92,5882.19 h52
  text "Bottom Solder Mask" at 6820,5733.23 h52
  text "(.GBS)" at 8163.05,5733.23 h52
  text "Solder Resist" at 9899.21,5733.23 h52
  text ".Layer_Name" at 577,-858.49 h60
M13 Component Bodies Top:
  text ".Layer_Name" at 577,-858.49 h60
M14 Component Bodies Bottom:
  text ".Layer_Name" at 577,-858.49 h60
M15 Courtyards Top:
  text ".Layer_Name" at 577,-858.49 h60
M16 Courtyards Bottom:
  text ".Layer_Name" at 577,-858.49 h60
Drill Drawing:
  text ".legend" at 3622.5,725.5 h60
  text "Drill Table" at 3647.5,540.5 h60
  text ".Layer_Name" at 577,-858.49 h60

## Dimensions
0,0 to 0,2800 on M2 Board Dimensions
0,0 to 3200,0 on M2 Board Dimensions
